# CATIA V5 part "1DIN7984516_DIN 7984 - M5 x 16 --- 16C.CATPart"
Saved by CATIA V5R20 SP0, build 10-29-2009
Part number: 1DIN7984516_DIN 7984 - M5 x 16 --- 16C
Revision: ANY
Definition: UNKNOWN
Nomenclature: 1DIN7984516_DIN 7984 - M5 x 16 --- 16C
Source: Unknown
Bounding box of the stored display mesh (mm): x 0 to 19.5, y -4.25 to 4.25, z -4.25 to 4.25
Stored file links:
  C:\Users\Utente\Desktop\IO LAVORO\3D X SITO CF\CUMSA\3D files PW\pw081230\pw081230_ejection\1DIN7984516_DIN 7984 - M5 x 16 --- 16C.CATPart
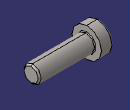
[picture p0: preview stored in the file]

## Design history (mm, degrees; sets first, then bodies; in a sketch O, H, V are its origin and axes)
Body1 "Hex" (main body)
  Solid1: solid without history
